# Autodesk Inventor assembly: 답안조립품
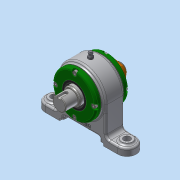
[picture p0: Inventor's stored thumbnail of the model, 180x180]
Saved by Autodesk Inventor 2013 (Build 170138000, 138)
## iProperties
Created: 2019-05
Part Number: 답안조립품
Document SubType Name: Assembly
Designer: dgall
Author: dgall
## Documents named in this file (13)
- C:\Users\dgall\Desktop\490504v1033\답안조립품.iam
- C:\Users\dgall\Desktop\490504v1033\본체.ipt
- C:\Users\dgall\Desktop\490504v1033\개스킷.ipt
- C:\Users\dgall\Desktop\490504v1033\그리스니플 M6.ipt
- 그리스니플  M6.ipt
- C:\Users\dgall\Desktop\490504v1033\그리스니플개스킷.ipt
- C:\Users\dgall\Desktop\490504v1033\베어링너트.ipt
- C:\Users\dgall\Desktop\490504v1033\볼트 M4.ipt
- C:\Users\dgall\Desktop\490504v1033\앵귤러 볼 베어링 7205.ipt
- C:\Users\dgall\Desktop\490504v1033\오일 실 28 40 5 B.ipt
- C:\Users\dgall\Desktop\490504v1033\축.ipt
- C:\Users\dgall\Desktop\490504v1033\칼라.ipt
- C:\Users\dgall\Desktop\490504v1033\커버.ipt
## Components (4 placed, 3 different names)
1. 개스킷:1
2. 그리스니플  M6:1
3. 그리스니플개스킷:1
4. 개스킷:2
